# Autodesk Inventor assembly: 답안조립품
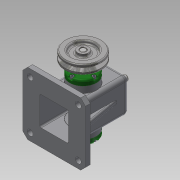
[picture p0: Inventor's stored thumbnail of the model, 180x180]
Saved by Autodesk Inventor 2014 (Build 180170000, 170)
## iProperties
Created: 2016-02
Part Number: 답안조립품
Document SubType Name: Assembly
Designer: user
Author: user
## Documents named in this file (16)
- C:\Users\user\Desktop\460212V1003\답안조립품.iam
- C:\Users\user\Desktop\460212V1003\본체.ipt
- C:\Users\user\Desktop\460212V1003\뒤커버.ipt
- C:\Users\user\Desktop\460212V1003\앞커버.ipt
- C:\Users\user\Desktop\460212V1003\편심축.ipt
- C:\Users\user\Desktop\460212V1003\베어링 12 x 32 x 10.ipt
- C:\Users\user\Desktop\460212V1003\링크.ipt
- C:\Users\user\Desktop\460212V1003\오일실 12 25 7.ipt
- C:\Users\user\Desktop\460212V1003\볼트 M4 x 12.ipt
- C:\Users\user\Desktop\460212V1003\키 4 x 4 x 10.ipt
- C:\Users\user\Desktop\460212V1003\V벨트풀리.ipt
- C:\Users\user\Desktop\460212V1003\멈춤나사 M3x8.ipt
- C:\Users\user\Desktop\460212V1003\슬라이드.ipt
- C:\Users\user\Desktop\460212V1003\핀 5 x 18.ipt
- C:\Users\user\Desktop\460212V1003\부시.ipt
- C:\Users\user\Desktop\460212V1003\고정핀 1.2 x 10.ipt
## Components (11 placed, 4 different names)
1. ISO 4762 M4 x 12:1 — Insert:8
2. ISO 4762 M4 x 12:2 — Insert:9
3. ISO 4762 M4 x 12:3 — Insert:10
4. ISO 4762 M4 x 12:4 — Insert:11
5. ISO 4762 M4 x 12:5 — Insert:12
6. ISO 4762 M4 x 12:6 — Insert:13
7. ISO 4762 M4 x 12:7 — Insert:14
8. ISO 4762 M4 x 12:8 — Insert:15
9. V벨트풀리:1 — Mate:3, Insert:18
10. 핀 5 x 18:1 — Insert:19, Tangent:1, Tangent:2
11. 고정핀 1.2 x 10:1 — Tangent:1, Tangent:2
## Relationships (13: Insert 10, Tangent 2, Mate 1)
- Insert:8: ISO 4762 M4 x 12:1
- Insert:9: ISO 4762 M4 x 12:2
- Insert:10: ISO 4762 M4 x 12:3
- Insert:11: ISO 4762 M4 x 12:4
- Insert:12: ISO 4762 M4 x 12:5
- Insert:13: ISO 4762 M4 x 12:6
- Insert:14: ISO 4762 M4 x 12:7
- Insert:15: ISO 4762 M4 x 12:8
- Mate:3: V벨트풀리:1
- Insert:18: V벨트풀리:1
- Insert:19: 핀 5 x 18:1
- Tangent:1: 핀 5 x 18:1 ↔ 고정핀 1.2 x 10:1
- Tangent:2: 핀 5 x 18:1 ↔ 고정핀 1.2 x 10:1
